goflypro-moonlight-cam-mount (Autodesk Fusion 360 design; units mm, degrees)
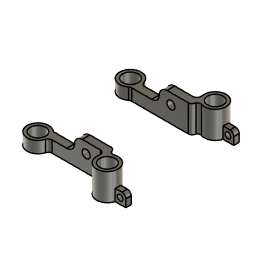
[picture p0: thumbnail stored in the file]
sketch "Skizze1" plane through (0, 0, 0) normal (0, 0, 1) x axis (1, 0, 0)
  line L1 (-8.0404, 2) -> (8, 2)
  line L2 (7.2, 0) -> (-7.2, 0)
  line L3 (7.2, 0) -> (7.2, -2)
  line L4 (8, -0.0404) -> (8, 2)
  line L5 (-0.5202, 0) -> (-0.5202, 2)
  circle C1 centre (-10, 0) radius 2
  circle C2 centre (10, -2) radius 2
  circle C3 centre (-10, 0) radius 2.8
  circle C4 centre (10, -2) radius 2.8
  point P8 (-7.2, 0)
  point P9 (7.2, -2)
  point P11 (8, -0.0404)
  point P7 (-8.0404, 2)
  point P13 (-0.5202, 0)
  concentric C1 C3
  concentric C2 C4
  horizontal L1
  coincident C3 P8
  horizontal L2
  coincident C4 P9
  tangent C4 L3
  perpendicular L2 L3
  coincident C4 P11
  perpendicular L1 L4
  coincident C3 P7
  coincident L2 P13
  dimension "d1" diameter C1 = 4
  dimension "d2" diameter C2 = 4
  dimension "d3" diameter C3 = 5.6
  dimension "d4" diameter C4 = 5.6
extrude "Extrusion1" new body sketch "Skizze1" profile of C2 C4 L1 L2 L3 L4 L5 along normal blind 7 bodies "GoFlyPro - Moonlight-cam mount - left"
extrude "Extrusion5" add sketch "Skizze1" profile of C1 C3 L1 L2 L5 along normal blind 3
sketch "Skizze2" plane through (0, 2, 0) normal (0, 1, 0) x axis (1, 0, 0)
  line L1 (0, -3.5) -> (0, -7.5)
  circle C1 centre (2.5, -4.25) radius 1.05
  circle C2 centre (7.0963, -8.1067) radius 1.05
  circle C3 centre (2.5, -4.25) radius 4.95
  circle C4 centre (2.5, -4.25) radius 7.05
  circle C5 centre (2.5, -10.25) radius 1.05
  concentric C1 C3
  tangent C2 C3
  concentric C3 C4
  tangent C2 C4
  vertical L1
  dimension "d8" diameter C1 = 2.1
  dimension "d31" diameter C2 = 2.1
  dimension "d32" diameter C5 = 2.1
extrude "Extrusion2" cut sketch "Skizze2" profile of C1 against normal blind 2
fillet "Abrundung12" radius 2
fillet "Abrundung13" radius 2
fillet "Abrundung14" radius 1
fillet "Abrundung15" radius 1
fillet "Abrundung16" radius 1
fillet "Abrundung17" radius 1
fillet "Abrundung18" radius 1
work_plane "Arbeitsebene" AlongDistance 12
sketch "Skizze3" plane through (0, 0, 0) normal (0, 0, 1) x axis (1, 0, 0)
  line L1 (12.5, -2.7) -> (15.5, -2.7)
  line L2 (12.5, -1.3) -> (12.5, -2.7)
  line L3 (15.5, -1.3) -> (12.5, -1.3)
  line L4 (15.5, -2.7) -> (15.5, -1.3)
  horizontal L1
  vertical L2
  horizontal L3
  vertical L4
extrude "Extrusion8" add sketch "Skizze3" along normal blind 3
sketch "Skizze4" plane through (0, -2.7, 0) normal (0, -1, 0) x axis (1, 0, 0)
  line L1 (12.7111, 0) -> (12.7111, 3)
  line L2 (15.5, 0) -> (12.7111, 0)
  line L3 (15.5, 3) -> (15.5, 0)
  line L4 (12.7111, 3) -> (15.5, 3)
  circle C1 centre (14, 1.5) radius 0.75
  dimension "d64" diameter C1 = 1.5
extrude "Extrusion9" cut sketch "Skizze4" profile of C1 against normal blind 2
fillet "Abrundung19" radius 1
mirror "Spiegeln" mirrorStitchTolerance 0.1 bodies "GoFlyPro - Moonlight-cam mount - right"
named bodies: "GoFlyPro - Moonlight-cam mount - left", "GoFlyPro - Moonlight-cam mount - right"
